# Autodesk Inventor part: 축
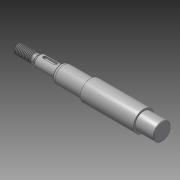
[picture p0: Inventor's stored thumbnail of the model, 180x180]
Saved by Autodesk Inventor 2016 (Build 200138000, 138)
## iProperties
Created: 2015-11
Part Number: 축
Material: 강철, 연강
Document SubType Name: Modeling
Designer: mduedu
Density: 1 g/cm^3
Appearance: 강철
Author: mduedu
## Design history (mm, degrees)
sketch "스케치1"
  geometry: L1 (-86, 0)-(86, 0); L2 (-86, 0)-(-86, 4); L3 (-86, 4)-(-70.732, 4); L4 (-70.732, 4)-(-69, 3); L5 (-69, 3)-(-67, 3); L6 (-67, 3)-(-67, 5); L7 (-67, 5)-(-49, 5); L8 (-49, 5)-(-49, 6.55); L9 (-47.355, 7.5)-(-23, 7.5); L10 (-23, 7.5)-(-23, 9); L11 (0, 0)-(0, 9); L12 (86, 4)-(70.732, 4); L13 (70.732, 4)-(69, 3); L14 (69, 3)-(67, 3); L15 (67, 3)-(67, 5); L16 (67, 5)-(49, 5); L17 (23, 7.5)-(23, 9); L18 (86, 0)-(86, 4); L19 (-23, 9)-(23, 9); L20 (-49, 6.55)-(-47.355, 7.5); L21 (47.355, 7.5)-(23, 7.5); L22 (49, 6.55)-(47.355, 7.5); L23 (49, 5)-(49, 6.55); 1 further point
  constraints: 46 end point, 10 symmetric about line, 6 perpendicular, 5 parallel, 2 midpoint, 1 coincident, 1 horizontal
  dimensions: "d0" = 172 distance of L1.start L1.end (derived); "d1" = 8 diameter of L3 L1; "d2" = 30 deg angle of L4 L5; "d3" = 6 diameter of L5 L1; "d4" = 10 diameter of L7 L1; "d5" = 15 diameter of L9 L1; "d6" = 18 diameter of L19 L1; "d8" = 18 distance of L6.end L7.end; "d9" = 46 distance of L10.end L17.end; "d10" = 2 distance of L4.end L5.end; "d11" = 17 distance from line of L4.end L2; "d16" = 13.1 diameter of L8.end L1; "d17" = 30 deg angle of L20 L9; "d18" = 26 distance between parallel lines of L10 L8
revolve "회전1" sketch "스케치1" stored, may be unused: angle "d12" = 90 deg
chamfer "모따기1" distance "d13" = 0.5; stored, may be unused: second distance "d14" = 2, angle "d15" = 45 deg
fillet "모깎기1" dims "d19" = 4, "d20" = 0.5
node "작업 평면1"
sketch "스케치2" dims "d23" = 12
  geometry: L1 (-4.5, 1.5)-(4.5, 1.5); L2 (4.5, 1.5)-(4.5, -1.5); L3 (4.5, -1.5)-(-4.5, -1.5); L4 (-4.5, -1.5)-(-4.5, 1.5); L5 (-9, -4.5)-(-9, 4.5) reference; 3 further points
  constraints: 8 end point, 2 midpoint, 2 parallel, 2 vertical alignment, 1 horizontal, 1 perpendicular, 4 other
  dimensions: "d21" = 3 distance between parallel lines of L3 L1; "d24" = 3 dimension on L5
extrude "돌출1" cut sketch "스케치2" distance "d25" = 1.8; taper "d26" = 0 deg
feature "스레드1" dims "d27" = 10, "d28" = 0
feature "스레드2" dims "d29" = 10, "d30" = 0
chamfer "모따기2" distance "d31" = 0.5; stored, may be unused: second distance "d32" = 2, angle "d33" = 45 deg
node "작업 평면2"
sketch "스케치3"
  geometry: C1 r 7.5 at (0, 0) reference; 1 further point
extrude "돌출2" cut sketch "스케치3" stored distance "d36" = 10; taper "d37" = 0 deg
chamfer "모따기3" distance "d38" = 0.5; stored, may be unused: second distance "d39" = 2, angle "d40" = 45 deg
fillet "모깎기3" dims "d41" = 0.6
node "솔리드1"
mirror "대칭1"
node "절단 모서리 투영1"
other parameters: "d35" = 16
